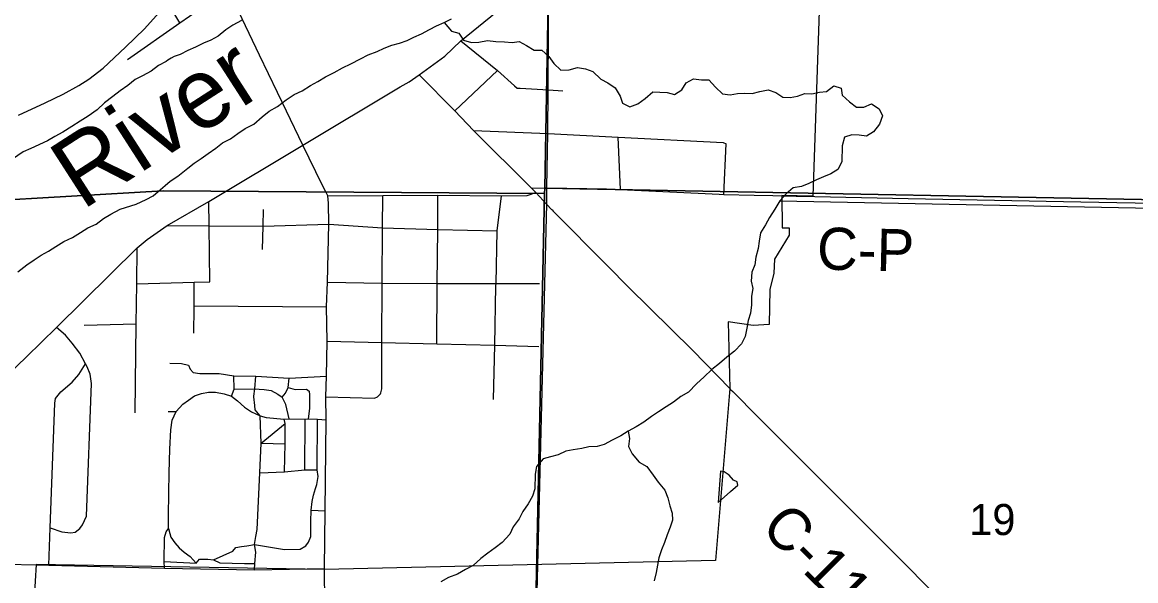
# Model space of a CAD drawing. Extents: x -6.2 to 37.4, y 0.2 to 22.2.
# Drawn here: x 2.552 to 3.302, y 16.626 to 17.002 of the extents above; entities that cross this region are included whole.
import ezdxf

# ---------------------------------------------------------------- set-up
doc = ezdxf.new("R2010")
doc.units = 0
for name, color, linetype in [('GM_X_City_Street', 7, 'Continuous'), ('GM_X_Corporation', 7, 'Continuous'), ('GM_X_County_Road', 7, 'Continuous'), ('GM_X_County_Road_Text', 7, 'Continuous'), ('GM_X_Major_River', 7, 'Continuous'), ('GM_X_Major_River_Text', 7, 'Continuous'), ('GM_X_Minor_Lake', 7, 'Continuous'), ('GM_X_Minor_River', 7, 'Continuous'), ('GM_X_Rail_Line', 7, 'Continuous'), ('GM_X_Section', 7, 'Continuous'), ('GM_X_Section_Text', 7, 'Continuous'), ('GM_X_State_Route', 7, 'Continuous'), ('GM_X_Township', 7, 'Continuous'), ('GM_X_Township_Road', 7, 'Continuous')]:
    doc.layers.add(name, color=color, linetype=linetype)

msp = doc.modelspace()

# ---------------------------------------------------------------- linework, layer by layer
at = {"layer": 'GM_X_City_Street'}
for p, q in [((2.84321, 16.94242), (2.87195, 16.96969)), ((2.95483, 16.88956), (2.95333, 16.92473)), ((3.0245, 16.88614), (3.02608, 16.92017)), ((2.66771, 16.81114), (2.7569, 16.81038)), ((2.59356, 16.79806), (2.62872, 16.79904))]:
    msp.add_line(p, q, dxfattribs=at)
for points in [[(2.62289, 16.97703), (2.65805, 17.00166), (2.6907, 17.02438)], [(2.65805, 17.00166), (2.64993, 17.01522), (2.64676, 17.02206), (2.64586, 17.02323)], [(2.84743, 16.98969), (2.87195, 16.96969), (2.88343, 16.95939), (2.88519, 16.95763), (2.88735, 16.95772), (2.90632, 16.95654), (2.91605, 16.95593)], [(2.85587, 16.92928), (2.90616, 16.92712), (2.95333, 16.92473), (3.024, 16.92115), (3.02608, 16.92017)], [(2.67822, 16.82728), (2.6778, 16.86502), (2.67762, 16.88129)], [(2.75772, 16.88512), (2.7948, 16.88539), (2.83193, 16.88567), (2.8748, 16.88514), (2.89206, 16.88544), (2.89775, 16.8875)], [(2.79209, 16.75058), (2.79325, 16.75172), (2.79357, 16.75242), (2.79405, 16.75522), (2.79423, 16.78635), (2.79446, 16.82633), (2.79467, 16.86357), (2.7948, 16.88539)], [(2.83121, 16.78544), (2.8315, 16.82624), (2.83176, 16.86261), (2.83193, 16.88567)], [(2.86938, 16.74807), (2.87016, 16.78449), (2.87101, 16.82468), (2.87104, 16.82615), (2.87179, 16.86158), (2.8748, 16.88514)], [(2.71378, 16.84915), (2.7142, 16.86481), (2.71451, 16.8761)], [(2.6496, 16.86519), (2.6778, 16.86502), (2.7142, 16.86481), (2.75842, 16.86611)], [(2.75842, 16.86611), (2.79467, 16.86357), (2.83176, 16.86261), (2.87179, 16.86158)], [(2.62795, 16.73905), (2.62872, 16.79904), (2.62907, 16.82599), (2.62938, 16.8502)], [(2.62907, 16.82599), (2.66783, 16.82701), (2.67822, 16.82728)], [(2.66756, 16.79259), (2.6677, 16.8098), (2.66771, 16.81114), (2.66783, 16.82701)], [(2.75746, 16.82713), (2.79446, 16.82633), (2.8315, 16.82624), (2.86658, 16.82616), (2.87104, 16.82615), (2.90034, 16.82609)], [(2.57079, 16.66151), (2.57869, 16.65873), (2.58456, 16.65807), (2.58761, 16.65859), (2.59068, 16.66101), (2.59262, 16.66364), (2.59518, 16.6693), (2.59864, 16.75867), (2.5978, 16.76514), (2.59565, 16.77002), (2.59448, 16.77203), (2.5908, 16.7793), (2.58559, 16.78602), (2.58112, 16.79141), (2.57495, 16.7966)], [(2.75725, 16.78725), (2.79423, 16.78635), (2.83121, 16.78544), (2.87016, 16.78449), (2.89979, 16.78376)], [(2.56984, 16.63628), (2.57079, 16.66151), (2.57396, 16.74557), (2.57438, 16.74861), (2.57787, 16.75311), (2.58556, 16.75963), (2.59001, 16.76488), (2.59448, 16.77203)], [(2.75644, 16.74987), (2.78926, 16.74891), (2.79114, 16.74978), (2.79209, 16.75058)]]:
    msp.add_lwpolyline(points, dxfattribs=at)
at = {"layer": 'GM_X_Corporation'}
msp.add_lwpolyline([(3.0913, 17.08851), (3.0845, 16.88501), (3.06365, 16.88536), (3.06367, 16.86357), (3.06841, 16.86357), (3.06845, 16.85878), (3.05853, 16.84253), (3.05814, 16.833), (3.05539, 16.82215), (3.05505, 16.79844), (3.04425, 16.79774), (3.0275, 16.80026), (3.02857, 16.75542), (3.01878, 16.63958), (2.75551, 16.63347), (2.56127, 16.63675), (2.55794, 16.58078)], dxfattribs=at)
at = {"layer": 'GM_X_County_Road'}
for p, q in [((3.07637, 16.88491), (3.0857, 16.88472)), ((2.69464, 16.75486), (2.7087, 16.75524)), ((2.65031, 16.7399), (2.65558, 16.73992)), ((2.7129, 16.71854), (2.7122, 16.73693)), ((2.7129, 16.71854), (2.72893, 16.73175)), ((2.74237, 16.7006), (2.74249, 16.73479)), ((2.75066, 16.7006), (2.75078, 16.73464)), ((2.71207, 16.69859), (2.7129, 16.71854)), ((2.7129, 16.71854), (2.72893, 16.71819)), ((2.74651, 16.67348), (2.75586, 16.67307)), ((2.64754, 16.63881), (2.66914, 16.63768))]:
    msp.add_line(p, q, dxfattribs=at)
for points in [[(2.54949, 16.93963), (2.56736, 16.94784), (2.57949, 16.95365), (2.59, 16.95954), (2.59689, 16.96383), (2.6064, 16.97118), (2.62155, 16.98534), (2.6343, 16.99774), (2.64993, 17.01522)], [(2.81928, 16.96665), (2.84321, 16.94242), (2.85587, 16.92928), (2.8949, 16.89034)], [(2.41652, 16.63941), (2.4508, 16.67683), (2.55476, 16.77672), (2.57495, 16.7966), (2.62938, 16.8502), (2.63598, 16.85573), (2.6496, 16.86519), (2.67762, 16.88129), (2.74084, 16.9194)], [(2.8949, 16.89034), (2.90461, 16.89054), (2.90542, 16.89052), (2.94542, 16.88985), (2.95483, 16.88956), (3.02123, 16.88622), (3.0245, 16.88614), (3.0448, 16.88565), (3.05753, 16.88535)], [(2.8949, 16.89034), (2.89775, 16.8875), (2.90531, 16.87943), (2.90847, 16.87606), (2.90882, 16.87569)], [(3.05753, 16.88535), (3.07309, 16.88498), (3.07451, 16.88494), (3.07637, 16.88491)], [(3.0857, 16.88472), (3.14869, 16.88343), (3.26493, 16.88106), (3.39871, 16.8787), (3.69013, 16.87288), (3.95882, 16.8683), (4.5241, 16.85938)], [(2.90882, 16.87569), (2.90952, 16.87494), (2.94624, 16.83791), (2.96027, 16.8236), (3.00329, 16.78127), (3.02869, 16.75514), (3.02905, 16.75479), (3.03048, 16.75335)], [(2.65143, 16.77245), (2.65922, 16.7722), (2.66399, 16.77119), (2.66512, 16.76843), (2.66701, 16.76617), (2.67153, 16.76554), (2.68133, 16.76544)], [(2.68133, 16.76544), (2.68459, 16.76541), (2.69439, 16.76392)], [(2.69288, 16.75034), (2.69464, 16.75486), (2.69439, 16.76392)], [(2.69439, 16.76392), (2.70925, 16.76379), (2.73169, 16.7624), (2.7569, 16.76372)], [(2.70802, 16.75033), (2.7087, 16.75524), (2.70925, 16.76379)], [(2.73169, 16.73502), (2.72943, 16.74456), (2.72704, 16.74959), (2.7293, 16.75235), (2.73106, 16.75599), (2.73169, 16.7624)], [(2.7087, 16.75524), (2.71147, 16.75486), (2.71499, 16.75474), (2.71963, 16.75398), (2.72415, 16.7516), (2.72704, 16.74959)], [(2.73106, 16.75599), (2.73571, 16.75474), (2.7435, 16.75486), (2.74525, 16.75361), (2.74551, 16.75122), (2.74551, 16.74896), (2.74538, 16.74193), (2.74451, 16.73486)], [(2.65558, 16.73992), (2.6601, 16.74494), (2.66387, 16.74758), (2.66801, 16.75047), (2.67279, 16.75197), (2.67731, 16.75298), (2.68221, 16.75285), (2.68786, 16.75185), (2.69288, 16.75034)], [(2.69288, 16.75034), (2.69703, 16.7472), (2.70167, 16.74293), (2.70645, 16.73966), (2.7122, 16.73693)], [(2.7122, 16.73693), (2.70883, 16.74105), (2.70858, 16.74394), (2.70795, 16.74984), (2.70802, 16.75033)], [(3.03048, 16.75335), (3.04762, 16.73615), (3.04834, 16.73544)], [(2.64767, 16.63429), (2.64754, 16.63881), (2.64767, 16.65501), (2.6488, 16.65891), (2.65043, 16.66104), (2.65055, 16.66946), (2.65068, 16.68516), (2.65093, 16.69859), (2.65131, 16.71442), (2.65194, 16.72761), (2.65282, 16.73401), (2.65558, 16.73992)], [(2.7122, 16.73693), (2.71624, 16.7359), (2.72845, 16.73464), (2.73169, 16.73502), (2.74249, 16.73479), (2.74451, 16.73486), (2.75078, 16.73464), (2.75656, 16.73439)], [(2.72862, 16.69924), (2.72893, 16.71819), (2.72893, 16.73175), (2.72845, 16.73464)], [(3.04834, 16.73544), (3.13747, 16.64621), (3.14494, 16.63865)], [(2.70833, 16.65024), (2.70934, 16.65564), (2.71009, 16.66041), (2.71207, 16.69859)], [(2.71207, 16.69859), (2.72862, 16.69924), (2.74237, 16.7006), (2.75066, 16.7006)], [(2.74651, 16.67348), (2.74726, 16.67938), (2.74814, 16.68352), (2.7494, 16.68805), (2.75028, 16.69068), (2.75116, 16.69608), (2.75066, 16.7006)], [(2.70833, 16.65024), (2.72868, 16.64685), (2.7391, 16.6471), (2.74287, 16.64936), (2.74475, 16.65187), (2.74638, 16.65564), (2.74626, 16.66569), (2.74651, 16.67348)], [(2.65043, 16.66104), (2.65131, 16.65778), (2.65206, 16.65514), (2.6547, 16.65137), (2.65771, 16.64811), (2.6611, 16.64522), (2.665, 16.64233), (2.66914, 16.63768)], [(2.66914, 16.63768), (2.67128, 16.64032), (2.67693, 16.64032), (2.6807, 16.64007), (2.69376, 16.64572), (2.69579, 16.64826), (2.69954, 16.64886), (2.7033, 16.64936), (2.70833, 16.65024)], [(2.70846, 16.6332), (2.70853, 16.63756), (2.70921, 16.64509), (2.70833, 16.65024)], [(2.6807, 16.64007), (2.68509, 16.63793), (2.70167, 16.63755), (2.70853, 16.63756)], [(3.14494, 16.63865), (3.23392, 16.54864), (3.36628, 16.41088)]]:
    msp.add_lwpolyline(points, dxfattribs=at)
at = {"layer": 'GM_X_Major_River'}
for points in [[(2.64822, 16.89212), (2.65162, 16.89499), (2.65685, 16.89842), (2.66344, 16.90374), (2.66767, 16.90726), (2.67243, 16.91025), (2.67723, 16.91376), (2.68222, 16.91726), (2.68681, 16.92094), (2.6922, 16.9237), (2.6972, 16.92721), (2.702, 16.93052), (2.70792, 16.93344), (2.71352, 16.93845), (2.71833, 16.94215), (2.72388, 16.94545), (2.72965, 16.94989), (2.73503, 16.95339), (2.74057, 16.95593), (2.74613, 16.95943), (2.75111, 16.96217), (2.75609, 16.9653), (2.76202, 16.96821), (2.76757, 16.97133), (2.77331, 16.97406), (2.77982, 16.97753), (2.78499, 16.98027), (2.7909, 16.98243), (2.79567, 16.98461), (2.80083, 16.9866), (2.80597, 16.98801), (2.81129, 16.98992), (2.8157, 16.99218), (2.82086, 16.99435), (2.82622, 16.99728), (2.831, 16.99965), (2.83616, 17.00201), (2.84113, 17.00438)], [(2.69954, 17.00342), (2.6938, 17.00012), (2.689, 16.99699), (2.6838, 16.99273), (2.67901, 16.98998), (2.67405, 16.98799), (2.66869, 16.98525), (2.66354, 16.98308), (2.65837, 16.98053), (2.65416, 16.97917), (2.65234, 16.97804), (2.64995, 16.9767)], [(2.64995, 16.9767), (2.64878, 16.9756), (2.64376, 16.97309), (2.6387, 16.96908), (2.63292, 16.96603), (2.62809, 16.96352), (2.62304, 16.9595), (2.6178, 16.95586), (2.61294, 16.95222), (2.6073, 16.94783), (2.60241, 16.94305), (2.59639, 16.93887), (2.59097, 16.93543), (2.58536, 16.932), (2.57936, 16.928), (2.57395, 16.92513), (2.56893, 16.92225), (2.55776, 16.91709), (2.55257, 16.91478), (2.54539, 16.90988)], [(2.57446, 16.85111), (2.57987, 16.85436), (2.58584, 16.85722), (2.59126, 16.86047), (2.5961, 16.86374), (2.60168, 16.86622), (2.60673, 16.86986), (2.61156, 16.87275), (2.61793, 16.87616), (2.62867, 16.87963), (2.6354, 16.88265), (2.64022, 16.88516), (2.64511, 16.88956), (2.64822, 16.89212)], [(2.54907, 16.83405), (2.5551, 16.8388), (2.55994, 16.84207), (2.56478, 16.84515), (2.56961, 16.84785), (2.57446, 16.85111)]]:
    msp.add_lwpolyline(points, dxfattribs=at)
at = {"layer": 'GM_X_Minor_Lake'}
msp.add_line((3.02215, 16.69971), (3.02076, 16.67868), dxfattribs=at)
msp.add_lwpolyline([(3.02076, 16.67868), (3.02886, 16.68591), (3.03388, 16.69037), (3.03335, 16.69246), (3.03091, 16.69365), (3.02796, 16.69712), (3.02479, 16.69927), (3.02215, 16.69971)], dxfattribs=at)
at = {"layer": 'GM_X_Minor_River'}
for points in [[(2.83616, 17.00201), (2.84115, 16.99603), (2.84604, 16.9948), (2.84916, 16.98999), (2.85443, 16.98856), (2.85954, 16.98884), (2.86524, 16.98986), (2.87091, 16.98918), (2.87677, 16.98887), (2.88187, 16.98858), (2.88662, 16.98924), (2.89167, 16.98649), (2.89672, 16.98335), (2.90182, 16.98325), (2.90666, 16.97917), (2.90997, 16.97436), (2.91479, 16.9699), (2.92028, 16.96998), (2.926, 16.97176), (2.93128, 16.97071), (2.93635, 16.9689), (2.94154, 16.96386), (2.94641, 16.9613), (2.95126, 16.95798), (2.95474, 16.95241), (2.95634, 16.94763), (2.96121, 16.94507), (2.96656, 16.94724), (2.97155, 16.95074), (2.97656, 16.9552), (2.98148, 16.9551), (2.9864, 16.95481), (2.99129, 16.95357), (2.99609, 16.95651), (2.99903, 16.96138), (3.00401, 16.96413), (3.00948, 16.96326), (3.0144, 16.96335), (3.01884, 16.95833), (3.02366, 16.95387), (3.02876, 16.9532), (3.0337, 16.95424), (3.03863, 16.95433), (3.04354, 16.95423), (3.04868, 16.95546), (3.05438, 16.95667), (3.05946, 16.95486), (3.06431, 16.95173), (3.06923, 16.95144), (3.07416, 16.95229), (3.07893, 16.9541), (3.08385, 16.954), (3.0888, 16.95504), (3.09354, 16.95551), (3.09854, 16.9592), (3.10343, 16.95778), (3.10408, 16.95302), (3.1091, 16.94856), (3.11394, 16.94486), (3.11887, 16.94495), (3.12402, 16.94712), (3.12906, 16.9438), (3.13142, 16.93901), (3.12942, 16.93355), (3.12533, 16.92832), (3.12054, 16.92538), (3.11563, 16.92604), (3.11072, 16.92633), (3.10576, 16.92472), (3.10413, 16.91888), (3.1039, 16.90807), (3.10134, 16.903), (3.09654, 16.90006), (3.09158, 16.89807), (3.08681, 16.89608), (3.08165, 16.89353), (3.07668, 16.89154), (3.07118, 16.8907), (3.06636, 16.88662), (3.06209, 16.88178), (3.05876, 16.87615), (3.05524, 16.87053), (3.05248, 16.86566), (3.04915, 16.86022), (3.04828, 16.85474), (3.04761, 16.84982), (3.04597, 16.84397), (3.0453, 16.83867), (3.0433, 16.83378), (3.04299, 16.82772), (3.04402, 16.82276), (3.04315, 16.81766), (3.04322, 16.81178), (3.04235, 16.8061), (3.04092, 16.8012), (3.04006, 16.79609), (3.0388, 16.79043), (3.03643, 16.78554), (3.03159, 16.78052), (3.0264, 16.77645), (3.02158, 16.77218)], [(3.06209, 16.88178), (3.33585, 16.87649), (3.33867, 16.87567), (3.33992, 16.87223), (3.33931, 16.87016), (3.33626, 16.77822)], [(3.02158, 16.77218), (3.01638, 16.76811), (3.01117, 16.76329), (3.00615, 16.75864), (3.00073, 16.75287), (2.99556, 16.74994), (2.99056, 16.74625), (2.98558, 16.74312), (2.98058, 16.73962), (2.97579, 16.73649), (2.9706, 16.7328), (2.96542, 16.72968), (2.96006, 16.72656), (2.95507, 16.72343), (2.94934, 16.72051), (2.94398, 16.71777), (2.93922, 16.71635), (2.93353, 16.71609), (2.92878, 16.71504), (2.92308, 16.71402), (2.91814, 16.71317), (2.91279, 16.71081), (2.90766, 16.7094), (2.9027, 16.70798), (2.89824, 16.70275), (2.89738, 16.69765), (2.89717, 16.68779), (2.89556, 16.68289), (2.8928, 16.67763), (2.8891, 16.67259), (2.88653, 16.6677), (2.88264, 16.66228), (2.88026, 16.65721), (2.87522, 16.65162), (2.87042, 16.64811), (2.86561, 16.64441), (2.8608, 16.6409), (2.85559, 16.63608), (2.85043, 16.63352), (2.84506, 16.63021), (2.83896, 16.62806), (2.83379, 16.62513)], [(2.96006, 16.72656), (2.96091, 16.7218), (2.96023, 16.71631), (2.96277, 16.71133), (2.96739, 16.70573), (2.97262, 16.70278), (2.97686, 16.69701), (2.98035, 16.6922), (2.98479, 16.68699), (2.98676, 16.68182), (2.98816, 16.67629), (2.98957, 16.67152), (2.98985, 16.66678), (2.98843, 16.66187), (2.98624, 16.65679), (2.98443, 16.65171), (2.98243, 16.64682), (2.98081, 16.64135), (2.97976, 16.63644), (2.97889, 16.63133), (2.97764, 16.62586)]]:
    msp.add_lwpolyline(points, dxfattribs=at)
at = {"layer": 'GM_X_Rail_Line'}
msp.add_lwpolyline([(2.87203, 15.37415), (2.88287, 15.8796), (2.89299, 16.38385), (2.90519, 16.87971), (2.9053, 16.8908), (2.90604, 16.9274), (2.9062, 16.95681), (2.90667, 17.03851), (2.90688, 17.07588), (2.91357, 17.34065), (2.91378, 17.35338), (2.92047, 17.7536), (2.92175, 17.83006), (2.92181, 17.83359), (2.92189, 17.83809), (2.92238, 17.86748), (2.92464, 17.99264), (2.93048, 18.21437), (2.93287, 18.3702)], dxfattribs=at)
at = {"layer": 'GM_X_Section'}
for points in [[(2.91294, 17.3873), (3.41225, 17.38056), (3.4002, 16.88095), (2.90397, 16.89028), (2.9126, 17.3784)], [(2.46846, 17.38053), (2.9126, 17.3784), (2.90397, 16.89028), (2.90372, 16.88668), (2.64683, 16.88866), (2.46132, 16.87779)], [(2.46132, 16.87779), (2.64683, 16.88866), (2.90372, 16.88668), (2.89317, 16.38663), (2.89289, 16.38152), (2.38563, 16.38809), (2.38968, 16.74498), (2.46127, 16.86472)], [(2.90397, 16.89028), (3.4002, 16.88095), (3.38994, 16.37612), (2.89317, 16.38663), (2.90372, 16.88668)]]:
    msp.add_lwpolyline(points, close=True, dxfattribs=at)
at = {"layer": 'GM_X_State_Route'}
msp.add_line((2.74084, 16.9194), (2.72987, 16.94219), dxfattribs=at)
for points in [[(2.84743, 16.98969), (2.90678, 17.03824), (2.91635, 17.04626), (2.92672, 17.05832), (2.93033, 17.06256)], [(2.72987, 16.94219), (2.71164, 16.98003), (2.6907, 17.02438)], [(2.81928, 16.96665), (2.83646, 16.97928), (2.84743, 16.98969)], [(2.74084, 16.9194), (2.80655, 16.95859), (2.81255, 16.96211), (2.81928, 16.96665)], [(2.75772, 16.88512), (2.75644, 16.88787), (2.75396, 16.89263), (2.74084, 16.9194)], [(2.75644, 16.74987), (2.7569, 16.76372), (2.75725, 16.78725), (2.7569, 16.81038), (2.75746, 16.82713), (2.75842, 16.86611), (2.7583, 16.88031), (2.75772, 16.88512)], [(2.75563, 16.63415), (2.75586, 16.67307), (2.75656, 16.73439), (2.75644, 16.74987)], [(2.76889, 15.37789), (2.76621, 15.51694), (2.76586, 15.54905), (2.76261, 15.80935), (2.76168, 15.88091), (2.75946, 16.10862), (2.75888, 16.19112), (2.75795, 16.297), (2.75679, 16.38334), (2.7569, 16.45979), (2.75609, 16.52576), (2.75574, 16.61024), (2.75563, 16.63415)]]:
    msp.add_lwpolyline(points, dxfattribs=at)
at = {"layer": 'GM_X_Township'}
msp.add_lwpolyline([(2.87203, 15.37415), (2.88287, 15.8796), (2.89299, 16.38385), (2.90519, 16.87971), (2.9053, 16.8908), (2.90604, 16.9274), (2.9062, 16.95681), (2.90667, 17.03851), (2.90688, 17.07588), (2.95747, 17.16618), (2.97346, 17.19773), (2.99272, 17.23206), (3.00624, 17.25417), (3.03562, 17.31049), (3.04867, 17.34024), (3.07941, 17.38888), (3.12118, 17.44688), (3.15222, 17.48363), (3.17947, 17.5104), (3.22997, 17.55435), (3.28508, 17.59881), (3.31666, 17.62007)], dxfattribs=at)
at = {"layer": 'GM_X_Township_Road'}
msp.add_line((2.54139, 16.63702), (2.56136, 16.6365), dxfattribs=at)
msp.add_lwpolyline([(2.56136, 16.6365), (2.56984, 16.63628), (2.64767, 16.63429), (2.70846, 16.6332), (2.75563, 16.63415)], dxfattribs=at)

# ---------------------------------------------------------------- texts
at = {"layer": 'GM_X_County_Road_Text'}
for s, rotation, p in [('C-P', 358.67876, (3.08697, 16.83562)), ('C-11C', 315.01023, (3.04852, 16.66059))]:
    msp.add_text(s, height=0.028409, rotation=rotation, dxfattribs=at).set_placement(p)
at = {"layer": 'GM_X_Major_River_Text'}
msp.add_text('River', height=0.047379, rotation=32.77512, dxfattribs=at).set_placement((2.59224, 16.8751))
at = {"layer": 'GM_X_Section_Text'}
msp.add_text('19', height=0.020928, rotation=0.00001, dxfattribs=at).set_placement((3.18977, 16.65666))

doc.saveas('drawing.dxf')
